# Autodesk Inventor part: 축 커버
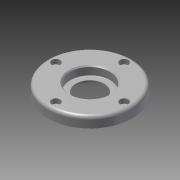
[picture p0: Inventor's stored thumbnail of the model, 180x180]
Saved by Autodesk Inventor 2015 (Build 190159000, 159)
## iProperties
Created: 2015-10
Part Number: 축 커버
Document SubType Name: Modeling
Designer: mdu
Density: 7.86 g/cm^3
Material: 강철, 연강
Mass: 322.464 g
Surface Area: 133.703 cm^2
Volume: 41.026 cm^3
Appearance: Steel
Author: mdu
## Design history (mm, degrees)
sketch "스케치1"
  geometry: C1 r 40 at (0, 0) reference; C2 r 26 at (0, 0) reference; 1 further point
  node "참조1"
  node "참조2"
extrude "돌출1" new body sketch "스케치1" distance "d0" = 10; taper "d1" = 0 deg
extrude "돌출2" join sketch "스케치1" distance "d2" = 3; taper "d3" = 0 deg
hole "구멍1" diameter "d6" = 27; stored, may be unused: countersink angle "d10" = 90 deg, drill point angle "d12" = 118 deg; dims "d4" = 10, "d5" = 10, "d7" = 6, "d8" = 38, "d9" = 8, "d11" = 8
sketch "스케치2"
  geometry: C1 r 20 at (0, 0); 1 further point
  constraints: 1 centre point, 1 coincident
  dimensions: "d13" = 40 diameter of C1
extrude "돌출3" cut sketch "스케치2" distance "d14" = 3; taper "d15" = 0 deg
sketch "스케치3"
  geometry: C1 r 1.621 at (0, 32.5) reference; 1 further point
hole "구멍2" sketch "스케치3" at (0, 32.5) diameter "d16" = 4.5; stored, may be unused: countersink angle "d20" = 90 deg, drill point angle "d22" = 118 deg; dims "d17" = 6, "d18" = 8, "d19" = 4.4, "d21" = 8
fillet "모깎기1" dims "d26" = 3, "d27" = 0.3
chamfer "모따기1" distance "d28" = 1; stored, may be unused: second distance "d29" = 2, angle "d30" = 45 deg
node "솔리드1"
pattern_circular "원형 패턴1" dims angle "d24" = 360 deg
node "참조3"
